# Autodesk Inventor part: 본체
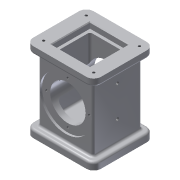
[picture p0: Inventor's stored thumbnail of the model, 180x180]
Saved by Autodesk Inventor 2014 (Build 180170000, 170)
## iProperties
Created: 2017-08
Part Number: 본체
Material: 알루미늄 6061
Document SubType Name: Modeling
Designer: user
Density: 2.71 g/cm^3
Appearance: 알루미늄 - 평지
Author: user
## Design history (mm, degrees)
sketch "스케치1"
  geometry: L1 (46, 41)-(-46, 41); L2 (-46, 41)-(-46, -41); L3 (-46, -41)-(46, -41); L4 (46, -41)-(46, 41); L5 (46, 41)-(-46, -41); L6 (-46, 41)-(46, -41); 1 further point
  constraints: 12 end point, 2 midpoint, 2 parallel, 1 horizontal, 1 perpendicular
  dimensions: "d0" = 92 distance of L2.end L3.end; "d1" = 82 distance of L1.end L2.end
extrude "돌출1" new body sketch "스케치1" distance "d2" = 10; taper "d3" = 0 deg
node "작업 평면1"
sketch "스케치2"
  geometry: L1 (37, -33)-(-37, -33); L2 (-37, -33)-(-37, 33); L3 (-37, 33)-(37, 33); L4 (37, 33)-(37, -33); L5 (37, -33)-(-37, 33); L6 (-37, -33)-(37, 33); 1 further point
  constraints: 12 end point, 2 midpoint, 2 parallel, 1 horizontal, 1 perpendicular
  dimensions: "d5" = 74 distance of L2.end L3.end; "d6" = 66 distance of L1.end L2.end
extrude "돌출2" join sketch "스케치2" stored distance "d7" = 88; taper "d8" = 0 deg
sketch "스케치3"
  geometry: L1 (-46, 41)-(46, 41); L2 (46, 41)-(46, -41); L3 (46, -41)-(-46, -41); L4 (-46, -41)-(-46, 41); L5 (-46, 41)-(46, -41); L6 (46, 41)-(-46, -41); 1 further point
  constraints: 12 end point, 2 midpoint, 2 parallel, 1 horizontal, 1 perpendicular
  dimensions: "d9" = 92 distance of L2.end L3.end; "d10" = 82 distance of L1.end L2.end
extrude "돌출3" join sketch "스케치3" distance "d11" = 10; taper "d12" = 0 deg
sketch "스케치4"
  geometry: C1 r 35 at (37, 44); 1 further point
  constraints: 1 centre point
  dimensions: "d13" = 70 diameter of C1
extrude "돌출4" cut sketch "스케치4" distance "d14" = 3; taper "d15" = 0 deg
sketch "스케치5"
  geometry: C1 r 35 at (0, 0) reference; 2 further points
  constraints: 1 coincident
hole "구멍1" sketch "스케치5" at (0, 0) diameter "d16" = 48; stored, may be unused: countersink angle "d20" = 90 deg, drill point angle "d22" = 0 deg; dims "d17" = 6, "d18" = 4, "d19" = 2, "d21" = 8
sketch "스케치6" dims "d23" = 58
  geometry: C1 r 35 at (0, 0) reference; 3 further points
  constraints: 1 coincident, 1 vertical alignment, 2 other
hole "구멍2" sketch "스케치6" at (0, 29) diameter "d24" = 3.242; stored, may be unused: countersink angle "d28" = 90 deg, drill point angle "d30" = 118 deg; dims "d25" = 4, "d26" = 4, "d27" = 2, "d29" = 6
sketch "스케치7"
  geometry: L1 (46, 41)-(-46, 41) reference; L2 (46, -41)-(46, 41) reference; L3 (0, 0)-(0, 41); L4 (0, 0)-(46, 0); 4 further points
  constraints: 4 end point, 2 midpoint, 2 symmetric about line
  dimensions: "d34" = 72 distance of point (-36, 31) point (36, 31); "d35" = 62 distance of point (36, 31) point (36, -31)
hole "구멍3" sketch "스케치7" at (-36, 31), (36, 31), (-35.443, -27.495), (36, -31) diameter "d36" = 3.242; stored, may be unused: countersink angle "d40" = 90 deg, drill point angle "d42" = 118 deg; dims "d37" = 4, "d38" = 4, "d39" = 2, "d41" = 6
sketch "스케치8"
  geometry: L1 (-46, 41)-(46, 41) reference; L2 (46, 41)-(46, -41) reference; L3 (0, 0)-(0, 41); L4 (0, 0)-(46, 0); 4 further points
  constraints: 4 end point, 2 midpoint, 2 symmetric about line
  dimensions: "d43" = 72 distance of point (36, 31) point (-36, 31); "d44" = 62 distance of point (36, -31) point (36, 31); "d45" = 62 distance of point (-36, -31) point (-36, 31); "d46" = 72 distance of point (36, -31) point (-36, -31)
hole "구멍4" sketch "스케치8" at (-36, 31), (36, 31), (36, -31), (-36, -31) diameter "d47" = 3.242; stored, may be unused: countersink angle "d51" = 90 deg, drill point angle "d53" = 118 deg; dims "d48" = 4, "d49" = 4, "d50" = 2, "d52" = 6
sketch "스케치9"
  geometry: L1 (-26, 26)-(26, 26); L2 (26, 26)-(26, -26); L3 (26, -26)-(-26, -26); L4 (-26, -26)-(-26, 26); L5 (-26, 26)-(26, -26); L6 (26, 26)-(-26, -26); 1 further point
  constraints: 12 end point, 2 midpoint, 2 parallel, 1 horizontal, 1 perpendicular
  dimensions: "d54" = 52 distance of L2.end L3.end; "d55" = 52 distance of L1.end L2.end
extrude "돌출5" cut sketch "스케치9" distance "d56" = 8; taper "d57" = 0 deg
sketch "스케치10"
  geometry: L1 (-22, 22)-(22, 22); L2 (22, 22)-(22, -22); L3 (22, -22)-(-22, -22); L4 (-22, -22)-(-22, 22); L5 (-22, 22)-(22, -22); L6 (22, 22)-(-22, -22); 1 further point
  constraints: 12 end point, 2 midpoint, 2 parallel, 1 horizontal, 1 perpendicular
  dimensions: "d58" = 44 distance of L2.end L3.end; "d59" = 44 distance of L1.end L2.end
extrude "돌출6" cut sketch "스케치10" distance "d60" = 74; taper "d61" = 0 deg
sketch "스케치11"
  geometry: L1 (-24, 24)-(24, 24); L2 (24, 24)-(24, -24); L3 (24, -24)-(-24, -24); L4 (-24, -24)-(-24, 24); L5 (-24, 24)-(24, -24); L6 (24, 24)-(-24, -24); 1 further point
  constraints: 12 end point, 2 midpoint, 2 parallel, 1 horizontal, 1 perpendicular
  dimensions: "d62" = 48 distance of L2.end L3.end; "d63" = 48 distance of L1.end L2.end
extrude "돌출7" cut sketch "스케치11" distance "d64" = 16; taper "d65" = 0 deg
sketch "스케치12"
  geometry: L1 (-8, -10)-(74, -10) reference; 2 further points
  dimensions: "d66" = 38 distance from line of L1 point (33, 28)
hole "구멍5" sketch "스케치12" at (33, 28) diameter "d67" = 4.134; stored, may be unused: countersink angle "d71" = 90 deg, drill point angle "d73" = 0 deg; dims "d68" = 25, "d69" = 4, "d70" = 2, "d72" = 6
sketch "스케치13"
  geometry: C1 r 2.067 at (33, 28) reference; 2 further points
  dimensions: "d74" = 42 distance of C1.centre point (33, 70)
hole "구멍6" sketch "스케치13" at (33, 70) diameter "d75" = 4.134; stored, may be unused: countersink angle "d79" = 90 deg, drill point angle "d81" = 0 deg; dims "d76" = 25, "d77" = 4, "d78" = 2, "d80" = 6
fillet "모깎기1" dims "d82" = 3
fillet "모깎기2" dims "d83" = 3
fillet "모깎기3" dims "d84" = 3
fillet "모깎기4" dims "d85" = 3
fillet "모깎기5" dims "d86" = 10
chamfer "모따기1" distance "d87" = 1; stored, may be unused: second distance "d88" = 2, angle "d89" = 45 deg
fillet "모깎기6" dims "d90" = 3
node "솔리드1"
mirror "대칭1"
pattern_circular "원형 패턴1" dims angle "d32" = 360 deg
mirror "대칭2"
other parameters: "d4" = 54
